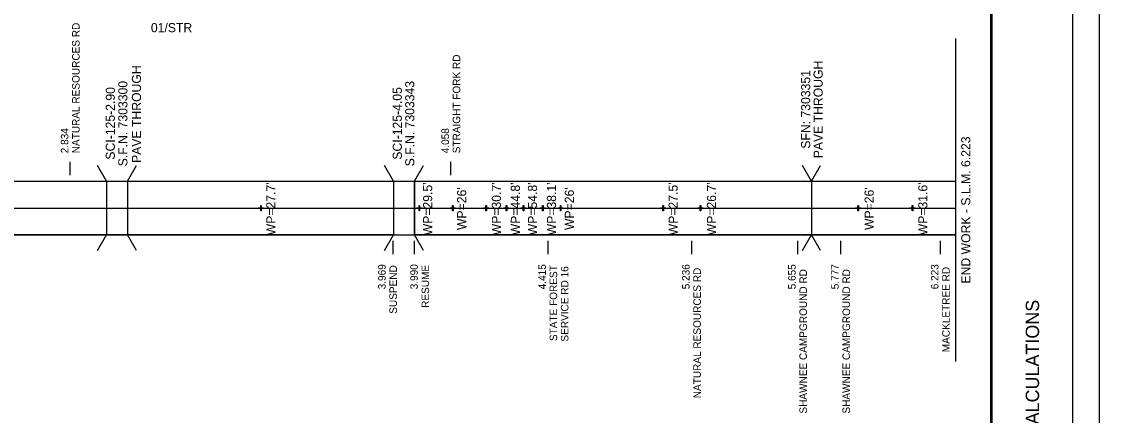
# Model space of a CAD drawing. Extents: x 0 to 34, y 0 to 31.9.
# Drawn here: x 13.9 to 34, y 13.21 to 20.55 of the extents above; entities that cross this region are included whole.
import ezdxf

# ---------------------------------------------------------------- set-up
doc = ezdxf.new("R2010")
doc.units = 0
for name, color, linetype in [('Default', 7, 'Continuous'), ('SH_Border', 7, 'Continuous'), ('SH_Cut_Line', 7, 'Continuous'), ('SH_Data', 7, 'Continuous'), ('SH_Text', 7, 'Continuous')]:
    doc.layers.add(name, color=color, linetype=linetype)

msp = doc.modelspace()

# ---------------------------------------------------------------- linework, layer by layer
at = {"layer": 'Default'}
for p, q in [((18.361, 17.124), (18.371, 17.124)), ((18.361, 17.079), (18.361, 17.124)), ((18.371, 17.079), (18.371, 17.124)), ((21.314, 17.124), (21.324, 17.124)), ((21.314, 17.079), (21.314, 17.124)), ((21.324, 17.079), (21.324, 17.124)), ((21.937, 17.124), (21.947, 17.124)), ((21.937, 17.079), (21.937, 17.124)), ((21.947, 17.079), (21.947, 17.124)), ((22.559, 17.124), (22.569, 17.124)), ((22.559, 17.079), (22.559, 17.124)), ((22.569, 17.079), (22.569, 17.124)), ((22.941, 17.124), (22.951, 17.124)), ((22.941, 17.079), (22.941, 17.124)), ((22.951, 17.079), (22.951, 17.124)), ((23.256, 17.124), (23.266, 17.124)), ((23.256, 17.079), (23.256, 17.124)), ((23.266, 17.079), (23.266, 17.124)), ((23.616, 17.124), (23.626, 17.124)), ((23.616, 17.079), (23.616, 17.124)), ((23.626, 17.079), (23.626, 17.124)), ((23.949, 17.124), (23.959, 17.124)), ((23.949, 17.079), (23.949, 17.124)), ((23.959, 17.079), (23.959, 17.124)), ((25.862, 17.124), (25.872, 17.124)), ((25.862, 17.079), (25.862, 17.124)), ((25.872, 17.079), (25.872, 17.124)), ((26.555, 17.124), (26.565, 17.124)), ((26.555, 17.079), (26.555, 17.124)), ((26.565, 17.079), (26.565, 17.124)), ((29.495, 17.124), (29.505, 17.124)), ((29.495, 17.079), (29.495, 17.124)), ((29.505, 17.079), (29.505, 17.124)), ((30.511, 17.124), (30.521, 17.124)), ((30.511, 17.079), (30.511, 17.124)), ((30.521, 17.079), (30.521, 17.124)), ((18.316, 17.079), (18.361, 17.079)), ((18.316, 17.079), (18.316, 17.069)), ((18.316, 17.069), (18.361, 17.069)), ((18.361, 17.074), (18.371, 17.074)), ((18.361, 17.024), (18.361, 17.069)), ((18.371, 17.024), (18.361, 17.024)), ((18.366, 17.069), (18.366, 17.079)), ((18.371, 17.079), (18.416, 17.079)), ((18.371, 17.024), (18.371, 17.069)), ((18.371, 17.069), (18.416, 17.069)), ((18.416, 17.079), (18.416, 17.069)), ((21.269, 17.079), (21.314, 17.079)), ((21.269, 17.079), (21.269, 17.069)), ((21.269, 17.069), (21.314, 17.069)), ((21.314, 17.074), (21.324, 17.074)), ((21.314, 17.024), (21.314, 17.069)), ((21.324, 17.024), (21.314, 17.024)), ((21.319, 17.069), (21.319, 17.079)), ((21.324, 17.079), (21.369, 17.079)), ((21.324, 17.024), (21.324, 17.069)), ((21.324, 17.069), (21.369, 17.069)), ((21.369, 17.079), (21.369, 17.069)), ((21.892, 17.079), (21.937, 17.079)), ((21.892, 17.079), (21.892, 17.069)), ((21.892, 17.069), (21.937, 17.069)), ((21.937, 17.074), (21.947, 17.074)), ((21.937, 17.024), (21.937, 17.069)), ((21.947, 17.024), (21.937, 17.024)), ((21.942, 17.069), (21.942, 17.079)), ((21.947, 17.079), (21.992, 17.079)), ((21.947, 17.024), (21.947, 17.069)), ((21.947, 17.069), (21.992, 17.069)), ((21.992, 17.079), (21.992, 17.069)), ((22.514, 17.079), (22.559, 17.079)), ((22.514, 17.079), (22.514, 17.069)), ((22.514, 17.069), (22.559, 17.069)), ((22.559, 17.074), (22.569, 17.074)), ((22.559, 17.024), (22.559, 17.069)), ((22.569, 17.024), (22.559, 17.024)), ((22.564, 17.069), (22.564, 17.079)), ((22.569, 17.079), (22.614, 17.079)), ((22.569, 17.024), (22.569, 17.069)), ((22.569, 17.069), (22.614, 17.069)), ((22.614, 17.079), (22.614, 17.069)), ((22.896, 17.079), (22.941, 17.079)), ((22.896, 17.079), (22.896, 17.069)), ((22.896, 17.069), (22.941, 17.069)), ((22.941, 17.074), (22.951, 17.074)), ((22.941, 17.024), (22.941, 17.069)), ((22.951, 17.024), (22.941, 17.024)), ((22.946, 17.069), (22.946, 17.079)), ((22.951, 17.079), (22.996, 17.079)), ((22.951, 17.024), (22.951, 17.069)), ((22.951, 17.069), (22.996, 17.069)), ((22.996, 17.079), (22.996, 17.069)), ((23.211, 17.079), (23.256, 17.079)), ((23.211, 17.079), (23.211, 17.069)), ((23.211, 17.069), (23.256, 17.069)), ((23.256, 17.074), (23.266, 17.074)), ((23.256, 17.024), (23.256, 17.069)), ((23.266, 17.024), (23.256, 17.024)), ((23.261, 17.069), (23.261, 17.079)), ((23.266, 17.079), (23.311, 17.079)), ((23.266, 17.024), (23.266, 17.069)), ((23.266, 17.069), (23.311, 17.069)), ((23.311, 17.079), (23.311, 17.069)), ((23.571, 17.079), (23.616, 17.079)), ((23.571, 17.079), (23.571, 17.069)), ((23.571, 17.069), (23.616, 17.069)), ((23.616, 17.074), (23.626, 17.074)), ((23.616, 17.024), (23.616, 17.069)), ((23.626, 17.024), (23.616, 17.024)), ((23.621, 17.069), (23.621, 17.079)), ((23.626, 17.079), (23.671, 17.079)), ((23.626, 17.024), (23.626, 17.069)), ((23.626, 17.069), (23.671, 17.069)), ((23.671, 17.079), (23.671, 17.069)), ((23.904, 17.079), (23.949, 17.079)), ((23.904, 17.079), (23.904, 17.069)), ((23.904, 17.069), (23.949, 17.069)), ((23.949, 17.074), (23.959, 17.074)), ((23.949, 17.024), (23.949, 17.069)), ((23.959, 17.024), (23.949, 17.024)), ((23.954, 17.069), (23.954, 17.079)), ((23.959, 17.079), (24.004, 17.079)), ((23.959, 17.024), (23.959, 17.069)), ((23.959, 17.069), (24.004, 17.069)), ((24.004, 17.079), (24.004, 17.069)), ((25.817, 17.079), (25.862, 17.079)), ((25.817, 17.079), (25.817, 17.069)), ((25.817, 17.069), (25.862, 17.069)), ((25.862, 17.074), (25.872, 17.074)), ((25.862, 17.024), (25.862, 17.069)), ((25.872, 17.024), (25.862, 17.024)), ((25.867, 17.069), (25.867, 17.079)), ((25.872, 17.079), (25.917, 17.079)), ((25.872, 17.024), (25.872, 17.069)), ((25.872, 17.069), (25.917, 17.069)), ((25.917, 17.079), (25.917, 17.069)), ((26.51, 17.079), (26.555, 17.079)), ((26.51, 17.079), (26.51, 17.069)), ((26.51, 17.069), (26.555, 17.069)), ((26.555, 17.074), (26.565, 17.074)), ((26.555, 17.024), (26.555, 17.069)), ((26.565, 17.024), (26.555, 17.024)), ((26.56, 17.069), (26.56, 17.079)), ((26.565, 17.079), (26.61, 17.079)), ((26.565, 17.024), (26.565, 17.069)), ((26.565, 17.069), (26.61, 17.069)), ((26.61, 17.079), (26.61, 17.069)), ((29.45, 17.079), (29.495, 17.079)), ((29.45, 17.079), (29.45, 17.069)), ((29.45, 17.069), (29.495, 17.069)), ((29.495, 17.074), (29.505, 17.074)), ((29.495, 17.024), (29.495, 17.069)), ((29.505, 17.024), (29.495, 17.024)), ((29.5, 17.069), (29.5, 17.079)), ((29.505, 17.079), (29.55, 17.079)), ((29.505, 17.024), (29.505, 17.069)), ((29.505, 17.069), (29.55, 17.069)), ((29.55, 17.079), (29.55, 17.069)), ((30.466, 17.079), (30.511, 17.079)), ((30.466, 17.079), (30.466, 17.069)), ((30.466, 17.069), (30.511, 17.069)), ((30.511, 17.074), (30.521, 17.074)), ((30.511, 17.024), (30.511, 17.069)), ((30.521, 17.024), (30.511, 17.024)), ((30.516, 17.069), (30.516, 17.079)), ((30.521, 17.079), (30.566, 17.079)), ((30.521, 17.024), (30.521, 17.069)), ((30.521, 17.069), (30.566, 17.069)), ((30.566, 17.079), (30.566, 17.069))]:
    msp.add_line(p, q, dxfattribs=at)
for points in [[(18.316, 17.069), (18.316, 17.079), (18.361, 17.079), (18.361, 17.124), (18.371, 17.124), (18.371, 17.079), (18.416, 17.079), (18.416, 17.069), (18.371, 17.069), (18.371, 17.024), (18.361, 17.024), (18.361, 17.069)], [(21.269, 17.069), (21.269, 17.079), (21.314, 17.079), (21.314, 17.124), (21.324, 17.124), (21.324, 17.079), (21.369, 17.079), (21.369, 17.069), (21.324, 17.069), (21.324, 17.024), (21.314, 17.024), (21.314, 17.069)], [(21.892, 17.069), (21.892, 17.079), (21.937, 17.079), (21.937, 17.124), (21.947, 17.124), (21.947, 17.079), (21.992, 17.079), (21.992, 17.069), (21.947, 17.069), (21.947, 17.024), (21.937, 17.024), (21.937, 17.069)], [(22.514, 17.069), (22.514, 17.079), (22.559, 17.079), (22.559, 17.124), (22.569, 17.124), (22.569, 17.079), (22.614, 17.079), (22.614, 17.069), (22.569, 17.069), (22.569, 17.024), (22.559, 17.024), (22.559, 17.069)], [(22.896, 17.069), (22.896, 17.079), (22.941, 17.079), (22.941, 17.124), (22.951, 17.124), (22.951, 17.079), (22.996, 17.079), (22.996, 17.069), (22.951, 17.069), (22.951, 17.024), (22.941, 17.024), (22.941, 17.069)], [(23.211, 17.069), (23.211, 17.079), (23.256, 17.079), (23.256, 17.124), (23.266, 17.124), (23.266, 17.079), (23.311, 17.079), (23.311, 17.069), (23.266, 17.069), (23.266, 17.024), (23.256, 17.024), (23.256, 17.069)], [(23.571, 17.069), (23.571, 17.079), (23.616, 17.079), (23.616, 17.124), (23.626, 17.124), (23.626, 17.079), (23.671, 17.079), (23.671, 17.069), (23.626, 17.069), (23.626, 17.024), (23.616, 17.024), (23.616, 17.069)], [(23.904, 17.069), (23.904, 17.079), (23.949, 17.079), (23.949, 17.124), (23.959, 17.124), (23.959, 17.079), (24.004, 17.079), (24.004, 17.069), (23.959, 17.069), (23.959, 17.024), (23.949, 17.024), (23.949, 17.069)], [(25.817, 17.069), (25.817, 17.079), (25.862, 17.079), (25.862, 17.124), (25.872, 17.124), (25.872, 17.079), (25.917, 17.079), (25.917, 17.069), (25.872, 17.069), (25.872, 17.024), (25.862, 17.024), (25.862, 17.069)], [(26.51, 17.069), (26.51, 17.079), (26.555, 17.079), (26.555, 17.124), (26.565, 17.124), (26.565, 17.079), (26.61, 17.079), (26.61, 17.069), (26.565, 17.069), (26.565, 17.024), (26.555, 17.024), (26.555, 17.069)], [(29.45, 17.069), (29.45, 17.079), (29.495, 17.079), (29.495, 17.124), (29.505, 17.124), (29.505, 17.079), (29.55, 17.079), (29.55, 17.069), (29.505, 17.069), (29.505, 17.024), (29.495, 17.024), (29.495, 17.069)], [(30.466, 17.069), (30.466, 17.079), (30.511, 17.079), (30.511, 17.124), (30.521, 17.124), (30.521, 17.079), (30.566, 17.079), (30.566, 17.069), (30.521, 17.069), (30.521, 17.024), (30.511, 17.024), (30.511, 17.069)]]:
    msp.add_lwpolyline(points, close=True, dxfattribs=at)
at = {"layer": 'SH_Border'}
msp.add_line((32, 0.5), (32, 21.5), dxfattribs=at)
msp.add_lwpolyline([(1.5, 21.5), (33.5, 21.5), (33.5, 0.5), (1.5, 0.5)], close=True, dxfattribs=at)
at = {"layer": 'SH_Cut_Line'}
msp.add_lwpolyline([(0, 0), (34, 0), (34, 22), (0, 22)], close=True, dxfattribs=at)
at = {"layer": 'SH_Text'}
for p, q in [((31.971, 21.5), (31.971, 0.516)), ((31.318, 20.232), (31.318, 14.211)), ((14.807, 17.687), (14.807, 17.937)), ((21.905, 17.687), (21.905, 17.937)), ((15.488, 17.574), (15.32, 17.864)), ((15.877, 17.574), (16.045, 17.864)), ((20.839, 17.574), (20.671, 17.864)), ((21.228, 17.574), (21.395, 17.864)), ((28.634, 17.574), (28.466, 17.864)), ((28.634, 17.574), (28.801, 17.864)), ((2.163, 17.574), (31.318, 17.574)), ((15.488, 17.574), (15.488, 16.575)), ((15.877, 17.574), (15.877, 16.575)), ((20.839, 17.574), (20.839, 16.575)), ((21.228, 17.574), (21.228, 16.575)), ((28.634, 17.574), (28.634, 16.575)), ((2.163, 17.074), (31.318, 17.072)), ((2.163, 16.576), (31.318, 16.576)), ((15.32, 16.285), (15.488, 16.575)), ((16.045, 16.285), (15.877, 16.575)), ((20.671, 16.285), (20.839, 16.575)), ((21.395, 16.285), (21.228, 16.575)), ((28.466, 16.285), (28.634, 16.575)), ((28.801, 16.285), (28.634, 16.575)), ((20.828, 16.462), (20.828, 16.212)), ((21.221, 16.462), (21.221, 16.212)), ((23.712, 16.462), (23.712, 16.212)), ((26.391, 16.462), (26.391, 16.212)), ((28.369, 16.462), (28.369, 16.212)), ((29.171, 16.462), (29.171, 16.212)), ((31.03, 16.462), (31.03, 16.212))]:
    msp.add_line(p, q, dxfattribs=at)
for points in [[(3.073, 17.574), (20.839, 17.574), (20.839, 16.575), (3.073, 16.575)], [(21.228, 17.574), (31.318, 17.574), (31.318, 16.575), (21.228, 16.575)]]:
    msp.add_lwpolyline(points, close=True, dxfattribs=at)

# ---------------------------------------------------------------- texts
at = {"layer": 'SH_Data'}
msp.add_text('PAVEMENT CALCULATIONS', height=0.25, rotation=90, dxfattribs=at).set_placement((32.875, 10.868))
at = {"layer": 'SH_Text'}
for s, height, p in [('NATURAL RESOURCES RD', 0.14, (14.985, 18.094)), ('STRAIGHT FORK RD', 0.14, (22.082, 18.094)), ('PAVE THROUGH', 0.17, (16.13, 17.914)), ('PAVE THROUGH', 0.17, (28.84, 18.001)), ('SFN: 7303351', 0.17, (28.607, 18.179)), ('SCI-125-2.90', 0.17, (15.642, 17.976)), ('S.F.N. 7303300', 0.17, (15.876, 17.851)), ('SCI-125-4.05', 0.17, (20.993, 17.975)), ('S.F.N. 7303343', 0.17, (21.226, 17.851)), ('2.834', 0.14, (14.775, 18.094)), ('4.058', 0.14, (21.872, 18.094)), ('END WORK - S.L.M. 6.223', 0.17, (31.593, 15.666)), ("WP=27.7'", 0.17, (18.635, 16.565)), ("WP=29.5'", 0.17, (21.559, 16.565)), ("WP=30.7'", 0.17, (22.841, 16.565)), ("WP=44.8'", 0.17, (23.195, 16.565)), ("WP=54.8'", 0.17, (23.514, 16.565)), ("WP=38.1'", 0.17, (23.868, 16.565)), ("WP=27.5'", 0.17, (26.136, 16.565)), ("WP=26.7'", 0.17, (26.851, 16.565)), ("WP=31.6'", 0.17, (30.792, 16.565)), ("WP=26'", 0.17, (22.193, 16.664)), ("WP=26'", 0.17, (24.201, 16.664)), ("WP=26'", 0.17, (29.791, 16.664)), ('3.969', 0.14, (20.691, 15.558)), ('SUSPEND', 0.14, (20.901, 15.104)), ('3.990', 0.14, (21.291, 15.559)), ('RESUME', 0.14, (21.501, 15.213)), ('4.415', 0.14, (23.679, 15.558)), ('STATE FOREST ', 0.14, (23.889, 14.594)), ('SERVICE RD 16', 0.14, (24.099, 14.584)), ('5.236', 0.14, (26.358, 15.559)), ('NATURAL RESOURCES RD', 0.14, (26.568, 13.528)), ('5.655', 0.14, (28.336, 15.558)), ('SHAWNEE CAMPGROUND RD', 0.14, (28.546, 13.242)), ('5.777', 0.14, (29.139, 15.559)), ('SHAWNEE CAMPGROUND RD', 0.14, (29.349, 13.242)), ('6.223', 0.14, (30.998, 15.559)), ('MACKLETREE RD', 0.14, (31.208, 14.386))]:
    msp.add_text(s, height=height, rotation=90, dxfattribs=at).set_placement(p)
msp.add_text('01/STR', height=0.17, dxfattribs=at).set_placement((16.314, 20.351))

doc.saveas('drawing.dxf')
